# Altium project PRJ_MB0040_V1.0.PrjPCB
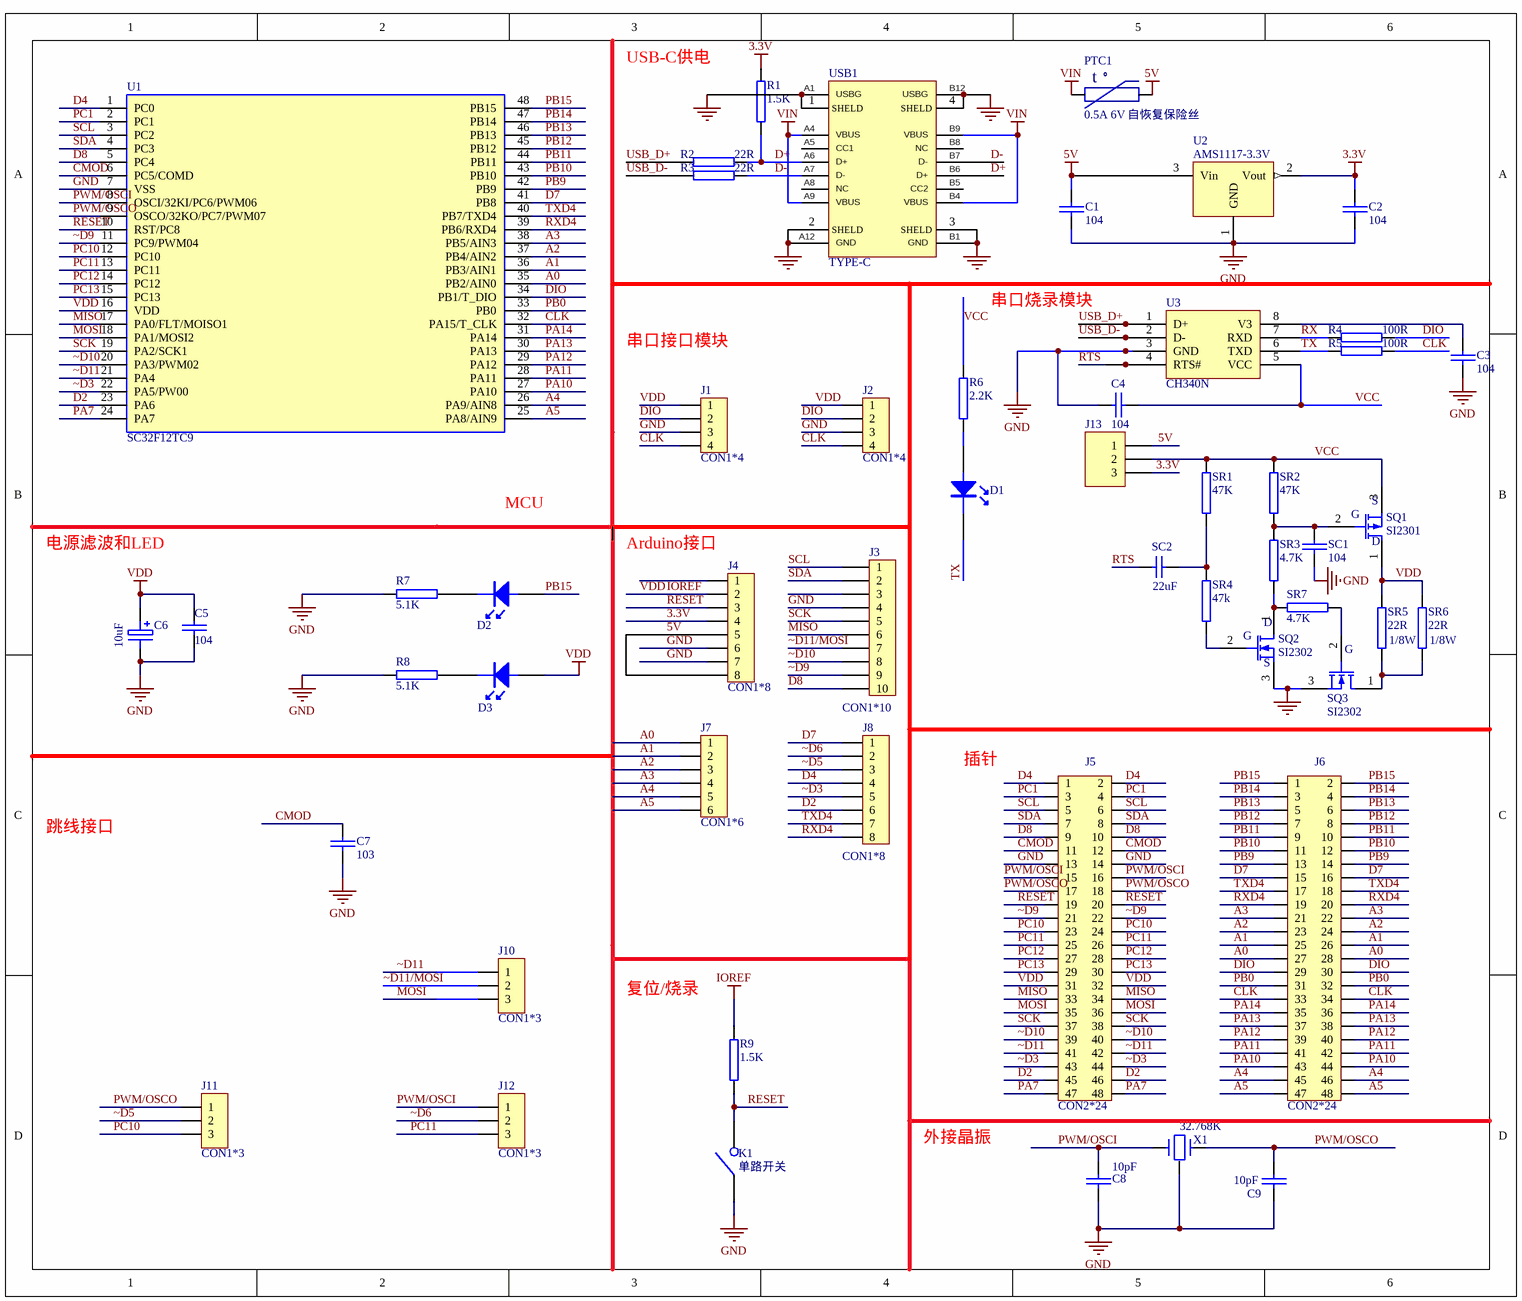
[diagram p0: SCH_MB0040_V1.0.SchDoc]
1 sheet, 52 parts. Net scope: global (net labels, ports and power ports of the same name join across sheets).
Board file: PCB_MB0040_V1.0.PcbDoc

## Sheet SCH_MB0040_V1.0.SchDoc
size 284 x 241 mm

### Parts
C1  104  [C0603]
C2  104  [C0603]
C3  104  [C0603]
C4  104  [C0603]
C5  104  [C0805]
C6  10uF  [A-3216]
C7  103  [C0805]
C8  10pF  [C0603]
C9  10pF  [C0603]
D1  LED-Bule  [LED0805]  (value not drawn)
D2  LED-Bule  [LED0805]  (value not drawn)
D3  LED-Yellow  [LED0805]  (value not drawn)
J1  CON1*4  [CON1*4(P=2.54)]
J2  CON1*4  [CON1*4(P=2.54)]
J3  CON1*10  [CON1*10(P=2.54)]
J4  CON1*8  [CON1*8(P=2.54)]
J5  CON2*24  [CON2*24(P=2.54)]
J6  CON2*24  [CON2*24(P=2.54)]
J7  CON1*6  [CON1*6(P=2.54)]
J8  CON1*8  [CON1*8(P=2.54)]
J10  CON1*3  [CON1*3(P=2.54)]
J11  CON1*3  [CON1*3(P=2.54)]
J12  CON1*3  [CON1*3(P=2.54)]
J13  Header 4  [CON1*3(P=2.54)]  (value not drawn)
K1  单路开关  [SW-SMD_UK-B0246-SP25Y]
PTC1  0.5A 6V 自恢复保险丝  [R1206]
R1  1.5K  [R0805]
R2  22R  [R0805]
R3  22R  [R0805]
R4  100R  [R0805]
R5  100R  [R0805]
R6  2.2K  [R0805]
R7  5.1K  [R0805]
R8  5.1K  [R0805]
R9  1.5K  [R0805]
SC1  104  [C0805]
SC2  value 22uF  [C0805]  (hidden comment: Cap)
SQ1  SI2301  [sanjiguan]
SQ2  SI2302  [sanjiguan]
SQ3  SI2302  [sanjiguan]
SR1  47K  [R0805]
SR2  47K  [R0805]
SR3  4.7K  [R0805]
SR4  47k  [R0805]
SR5  22R  功率: 1/8W  [R0805]
SR6  22R  功率: 1/8W  [R0805]
SR7  4.7K  [R0805]
U1  SC32F12TC9  [CH48]
U2  AMS1117-3.3V  [AMS1117-3.3V]
U3  CH340N  [CH8]
USB1  TYPE-C  [TYPE-C1]
X1  32.768K  [32768]

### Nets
3.3V: C2.1 J4.4 J13.3 R1.1 U2.2(Vout)
5V: C1.1 J4.5 J4.8 J13.1 PTC1.2 U2.3(Vin)
GND: C1.2 C2.2 C3.2 C4.2 C5.2 C6.2 C7.2 C8.2 C9.2 J1.3 J2.3 J3.4 J4.6 J4.7 J5.13 J5.14 K1.1 R7.2 R8.2 SC1.2 SQ2.3(S) SQ3.3(S) U1.7(VSS) U2.1(GND) U3.3(GND) USB1.1(SHELD) USB1.2(SHELD) USB1.3(SHELD) USB1.4(SHELD) USB1.A1(USBG) USB1.A12(GND) USB1.B1(GND) USB1.B12(USBG) X1.0
IOREF: C5.1 C6.1 D3.1 J1.1 J2.1 J4.2 J5.31 J5.32 R9.2 SQ1.1(D) SR5.2 SR6.2 U1.16(VDD)  [also labelled VDD]
VIN: PTC1.1 USB1.A4(VBUS) USB1.A9(VBUS) USB1.B4(VBUS) USB1.B9(VBUS)
A0: J6.27 J6.28 J7.1 U1.35(PB2/AIN0)
A1: J6.25 J6.26 J7.2 U1.36(PB3/AIN1)
A2: J6.23 J6.24 J7.3 U1.37(PB4/AIN2)
A3: J6.21 J6.22 J7.4 U1.38(PB5/AIN3)
A4: J6.45 J6.46 J7.5 U1.26(PA9/AIN8)
A5: J6.47 J6.48 J7.6 U1.25(PA8/AIN9)
CLK: J1.4 J2.4 J6.33 J6.34 R5.1 U1.32(PA15/T_CLK)
CMOD: C7.1 J5.11 J5.12 U1.6(PC5/COMD)
D2: J5.45 J5.46 J8.6 U1.23(PA6)
D4: J5.1 J5.2 J8.4 U1.1(PC0)
D7: J6.15 J6.16 J8.1 U1.41(PB8)
D8: J3.10 J5.9 J5.10 U1.5(PC4)
D+: R1.2 R2.1 USB1.A6(D+) USB1.B6(D+)
D-: R3.1 USB1.A7(D-) USB1.B7(D-)
DIO: J1.2 J2.2 J6.29 J6.30 R4.1 U1.34(PB1/T_DIO)
MISO: J3.6 J5.33 J5.34 U1.17(PA0/FLT/MOISO1)
MOSI: J5.35 J5.36 J10.3 U1.18(PA1/MOSI2)
PA7: J5.47 J5.48 U1.24(PA7)
PA10: J6.43 J6.44 U1.27(PA10)
PA11: J6.41 J6.42 U1.28(PA11)
PA12: J6.39 J6.40 U1.29(PA12)
PA13: J6.37 J6.38 U1.30(PA13)
PA14: J6.35 J6.36 U1.31(PA14)
PB0: J6.31 J6.32 U1.33(PB0)
PB9: J6.13 J6.14 U1.42(PB9)
PB10: J6.11 J6.12 U1.43(PB10)
PB11: J6.9 J6.10 U1.44(PB11)
PB12: J6.7 J6.8 U1.45(PB12)
PB13: J6.5 J6.6 U1.46(PB13)
PB14: J6.3 J6.4 U1.47(PB14)
PB15: D2.1 J6.1 J6.2 U1.48(PB15)
PC1: J5.3 J5.4 U1.2(PC1)
PC10: J5.23 J5.24 J11.3 U1.12(PC10)
PC11: J5.25 J5.26 J12.3 U1.13(PC11)
PC12: J5.27 J5.28 U1.14(PC12)
PC13: J5.29 J5.30 U1.15(PC13)
PWM/OSCI: C8.1 J5.15 J5.16 J12.1 U1.8(OSCI/32KI/PC6/PWM06) X1.1
PWM/OSCO: C9.1 J5.17 J5.18 J11.1 U1.9(OSCO/32KO/PC7/PWM07) X1.2
RESET: J4.3 J5.19 J5.20 K1.2 R9.1 U1.10(RST/PC8)
RTS: SC2.1 U3.4(RTS#)
RX: R4.2 U3.7(RXD)
RXD4: J6.19 J6.20 J8.8 U1.39(PB6/RXD4)
SCK: J3.5 J5.37 J5.38 U1.19(PA2/SCK1)
SCL: J3.1 J5.5 J5.6 U1.3(PC2)
SDA: J3.2 J5.7 J5.8 U1.4(PC3)
TX: D1.2 R5.2 U3.6(TXD)
TXD4: J6.17 J6.18 J8.7 U1.40(PB7/TXD4)
USB_D+: R2.2 U3.1(D+)
USB_D-: R3.2 U3.2(D-)
VCC: C4.1 J13.2 R6.1 SQ1.3(S) SR1.2 SR2.1 U3.5(VCC)
~D3: J5.43 J5.44 J8.5 U1.22(PA5/PW00)
~D5: J8.3 J11.2
~D6: J8.2 J12.2
~D9: J3.9 J5.21 J5.22 U1.11(PC9/PWM04)
~D10: J3.8 J5.39 J5.40 U1.20(PA3/PWM02)
~D11: J5.41 J5.42 J10.1 U1.21(PA4)
~D11/MOSI: J3.7 J10.2
NetC3_1: C3.1 U3.8(V3)
NetD1_1: D1.1 R6.2
NetD2_2: D2.2 R7.1
NetD3_2: D3.2 R8.1
NetSC1_1: SC1.1 SQ1.2(G) SR2.2 SR3.2
NetSC2_2: SC2.2 SR1.1 SR4.2
NetSQ2_1: SQ2.1(D) SR3.1 SR7.2
NetSQ2_2: SQ2.2(G) SR4.1
NetSQ3_1: SQ3.1(D) SR5.1 SR6.1
NetSQ3_2: SQ3.2(G) SR7.1

Not connected (* = marked no-connect by the designer): J3 3; J4 1; USB1 A5(CC1) A8(NC) B5(CC2) B8(NC)

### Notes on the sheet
- USB-C供电
- 串口烧录模块
- 串口接口模块
- MCU
- (near SQ1) S
- 电源滤波和LED
- (near J4) Arduino接口
- (near SQ1) G
- (near SQ1) D
- (near SQ2) G
- (near SQ2) D
- (near SQ2) S
- (near SQ3) G
- 插针
- 跳线接口
- 复位/烧录
- 外接晶振

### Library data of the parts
C1-C5 C7-C9 SC1 = CAP1: 贴片电容
C6 = T-A/4.7uF/16V
D1 D2 = LED-CP: 蓝色
D3 = LED-CP: 黄色
J13 = Header 3: Header, 3-Pin
K1 = KEY-6
PTC1 = PTC-MZ11-06A200-400RM: 6V 500mA PTC自恢复保险丝
R1-R9 SR1-SR4 SR7 = R0805: 功率: 1/8W
SC2 = Cap: Capacitor
SQ1 = MOSFET-P: P-Channel MOSFET
SQ2 SQ3 = MOSFET-N: N-Channel MOSFET
SR5 SR6 = R0805
U1 = SC32F12TC9: SC32F12TC9/48PIN
U2 = LDO-SPX1117M3: LDO；1A；SOT-223-3
USB1 = TYPE-C1: Type-c母座16pin 快充闪充usb3.0沉板母座连接器
X1 = CRYSTAL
